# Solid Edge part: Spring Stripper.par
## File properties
Author: Dan
Template: Normal.par
Last saved by: Dan
Revision: 135
Application: Solid Edge
Density: 7.850 kg/dm^3
Accuracy: 0.99
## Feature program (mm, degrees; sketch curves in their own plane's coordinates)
helix protrusion "HelixProtrusion_1"  NumberOfTurns = 4
helix protrusion "HelixProtrusion_2"  NumberOfTurns = 1
helix protrusion "HelixProtrusion_3"  NumberOfTurns = 1
sketch for "unnamed Cutout 1" plane through (0, 0, 0) normal (0, -1, 0) x-axis (1, 0, 0)
  line (-17, 12.5) -> (-17, 6.5)
extrude "unnamed Cutout 1" cut through
sketch for "unnamed Cutout 2" plane through (0, 0, 0) normal (0, -1, 0) x-axis (1, 0, 0)
  line (13, 6.5) -> (13, 12.5)
extrude "unnamed Cutout 2" cut through
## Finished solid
Body 1: solid body, 8 faces, 18 edges, 12 vertices.
  Faces by surface: spline 4, cylinder 2, plane 2
  Edges by curve: spline 8, circle 4, line 4, intersection 2
Bounding box of the edges (mm; curved faces can reach further): 30.000 x 25.000 x 25.000, from (-17, -12.5, -12.5) to (13, 12.5, 12.5).
Cylindrical faces by radius (mm): R6.5 x1, R12.5 x1
Planar faces by outward normal: +x 1, -x 1
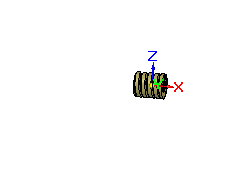
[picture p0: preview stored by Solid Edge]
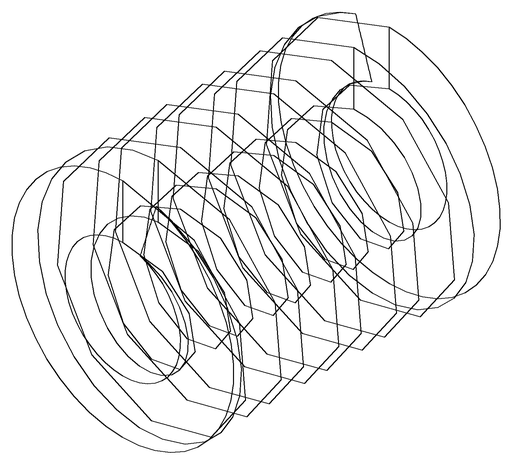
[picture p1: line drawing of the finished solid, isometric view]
